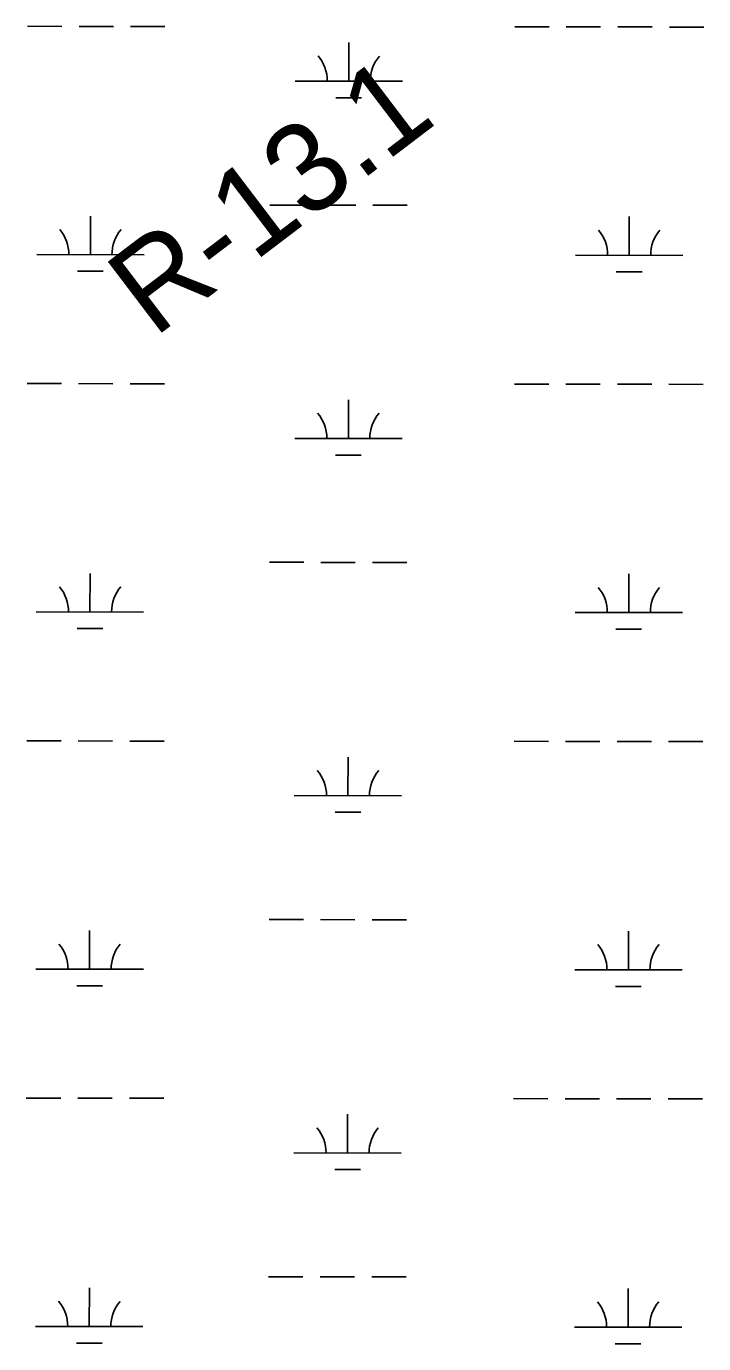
# Model space of a CAD drawing. Extents: x 3148686 to 3186545, y 916144 to 941516.
# Drawn here: x 3158954 to 3159585, y 937389 to 938615 of the extents above; entities that cross this region are included whole.
import ezdxf

# ---------------------------------------------------------------- set-up
doc = ezdxf.new("R2010")
doc.units = 0
doc.layers.add('V-RIVR-RANG-IDEN', color=7, linetype='Continuous')
doc.layers.add('V-WETL-SWMP', color=7, linetype='Continuous')

msp = doc.modelspace()

# ---------------------------------------------------------------- linework, layer by layer
at = {"layer": 'V-WETL-SWMP'}
for p, q in [((3158955.2, 938615.2), (3158987.2, 938615.1)), ((3159003.2, 938615.1), (3159035.2, 938615.1)), ((3159051.2, 938615.1), (3159083.2, 938615)), ((3159409.1, 938614.7), (3159441.1, 938614.7)), ((3159457.1, 938614.7), (3159489.1, 938614.6)), ((3159505.1, 938614.6), (3159537.1, 938614.6)), ((3159553.1, 938614.5), (3159585.1, 938614.5)), ((3159254.4, 938564.1), (3159254.5, 938600.1)), ((3159204.4, 938564.2), (3159304.4, 938564.1)), ((3159242.4, 938548.7), (3159266.4, 938548.7)), ((3159180.9, 938448.8), (3159212.9, 938448.7)), ((3159228.9, 938448.7), (3159260.9, 938448.7)), ((3159276.9, 938448.7), (3159308.9, 938448.6)), ((3159013.8, 938402.5), (3159013.8, 938438.5)), ((3159515.7, 938402), (3159515.7, 938438)), ((3158963.8, 938402.6), (3159063.8, 938402.5)), ((3159465.7, 938402), (3159565.7, 938401.9)), ((3159001.8, 938387.1), (3159025.8, 938387.1)), ((3159503.7, 938386.6), (3159527.7, 938386.5)), ((3158954.8, 938282.5), (3158986.8, 938282.5)), ((3159002.8, 938282.5), (3159034.8, 938282.4)), ((3159050.8, 938282.4), (3159082.8, 938282.4)), ((3159408.7, 938282), (3159440.7, 938282)), ((3159456.7, 938282), (3159488.7, 938281.9)), ((3159504.7, 938281.9), (3159536.7, 938281.9)), ((3159552.7, 938281.9), (3159584.7, 938281.8)), ((3159254.1, 938231.4), (3159254.1, 938267.4)), ((3159204.1, 938231.5), (3159304.1, 938231.4)), ((3159242.1, 938216), (3159266.1, 938216)), ((3159180.5, 938116.1), (3159212.5, 938116.1)), ((3159228.5, 938116), (3159260.5, 938116)), ((3159276.5, 938116), (3159308.5, 938116)), ((3159013.4, 938069.8), (3159013.5, 938105.8)), ((3159515.3, 938069.3), (3159515.4, 938105.3)), ((3158963.4, 938069.9), (3159063.4, 938069.8)), ((3159465.3, 938069.4), (3159565.3, 938069.3)), ((3159001.4, 938054.4), (3159025.4, 938054.4)), ((3159503.3, 938053.9), (3159527.3, 938053.9)), ((3158954.5, 937949.8), (3158986.5, 937949.8)), ((3159002.5, 937949.8), (3159034.5, 937949.7)), ((3159050.5, 937949.7), (3159082.5, 937949.7)), ((3159408.4, 937949.4), (3159440.4, 937949.3)), ((3159456.4, 937949.3), (3159488.4, 937949.3)), ((3159504.4, 937949.3), (3159536.4, 937949.2)), ((3159552.4, 937949.2), (3159584.4, 937949.2)), ((3159253.7, 937898.8), (3159253.8, 937934.8)), ((3159203.7, 937898.8), (3159303.7, 937898.7)), ((3159241.7, 937883.4), (3159265.7, 937883.3)), ((3159013.1, 937737.2), (3159013.1, 937773.2)), ((3159180.2, 937783.4), (3159212.2, 937783.4)), ((3159228.2, 937783.4), (3159260.2, 937783.3)), ((3159276.2, 937783.3), (3159308.2, 937783.3)), ((3159515, 937736.6), (3159515, 937772.6)), ((3158963.1, 937737.2), (3159063.1, 937737.1)), ((3159465, 937736.7), (3159565, 937736.6)), ((3159001.1, 937721.7), (3159025.1, 937721.7)), ((3159503, 937721.2), (3159527, 937721.2)), ((3158954.1, 937617.2), (3158986.1, 937617.1)), ((3159002.1, 937617.1), (3159034.1, 937617.1)), ((3159050.1, 937617.1), (3159082.1, 937617)), ((3159408, 937616.7), (3159440, 937616.6)), ((3159456, 937616.6), (3159488, 937616.6)), ((3159504, 937616.6), (3159536, 937616.5)), ((3159552, 937616.5), (3159584, 937616.5)), ((3159253.4, 937566.1), (3159253.4, 937602.1)), ((3159203.4, 937566.2), (3159303.4, 937566)), ((3159241.4, 937550.7), (3159265.4, 937550.7)), ((3159012.7, 937404.5), (3159012.8, 937440.5)), ((3159179.8, 937450.7), (3159211.8, 937450.7)), ((3159227.8, 937450.7), (3159259.8, 937450.7)), ((3159275.8, 937450.6), (3159307.8, 937450.6)), ((3159514.6, 937404), (3159514.7, 937440)), ((3158962.7, 937404.5), (3159062.7, 937404.4)), ((3159464.6, 937404), (3159564.6, 937403.9)), ((3159000.7, 937389.1), (3159024.7, 937389)), ((3159502.6, 937388.5), (3159526.6, 937388.5))]:
    msp.add_line(p, q, dxfattribs=at)
for centre, start, end in [((3159199.2, 938564.7), 359.1678, 40.7115), ((3159309.7, 938564.5), 139.1678, 180.7115), ((3158958.5, 938403), 359.1678, 40.7115), ((3159069, 938402.9), 139.1678, 180.7115), ((3159460.4, 938402.5), 359.1678, 40.7115), ((3159570.9, 938402.4), 139.1678, 180.7115), ((3159198.8, 938232), 359.1678, 40.7115), ((3159309.3, 938231.9), 139.1678, 180.7115), ((3158958.2, 938070.4), 359.1678, 40.7115), ((3159068.7, 938070.3), 139.1678, 180.7115), ((3159460.1, 938069.8), 359.1678, 40.7115), ((3159570.6, 938069.7), 139.1678, 180.7115), ((3159198.5, 937899.3), 359.1678, 40.7115), ((3159309, 937899.2), 139.1678, 180.7115), ((3158957.8, 937737.7), 359.1678, 40.7115), ((3159068.3, 937737.6), 139.1678, 180.7115), ((3159459.7, 937737.2), 359.1678, 40.7115), ((3159570.2, 937737.1), 139.1678, 180.7115), ((3159198.1, 937566.6), 359.1678, 40.7115), ((3159308.6, 937566.5), 139.1678, 180.7115), ((3158957.5, 937405), 359.1678, 40.7115), ((3159068, 937404.9), 139.1678, 180.7115), ((3159459.4, 937404.5), 359.1678, 40.7115), ((3159569.9, 937404.4), 139.1678, 180.7115)]:
    msp.add_arc(centre, 35.2, start, end, dxfattribs=at)

# ---------------------------------------------------------------- texts
at = {"layer": 'V-RIVR-RANG-IDEN'}
msp.add_text('R-13.1', height=83, rotation=37.2377, dxfattribs=at).set_placement((3159073, 938324.4))

doc.saveas('drawing.dxf')
